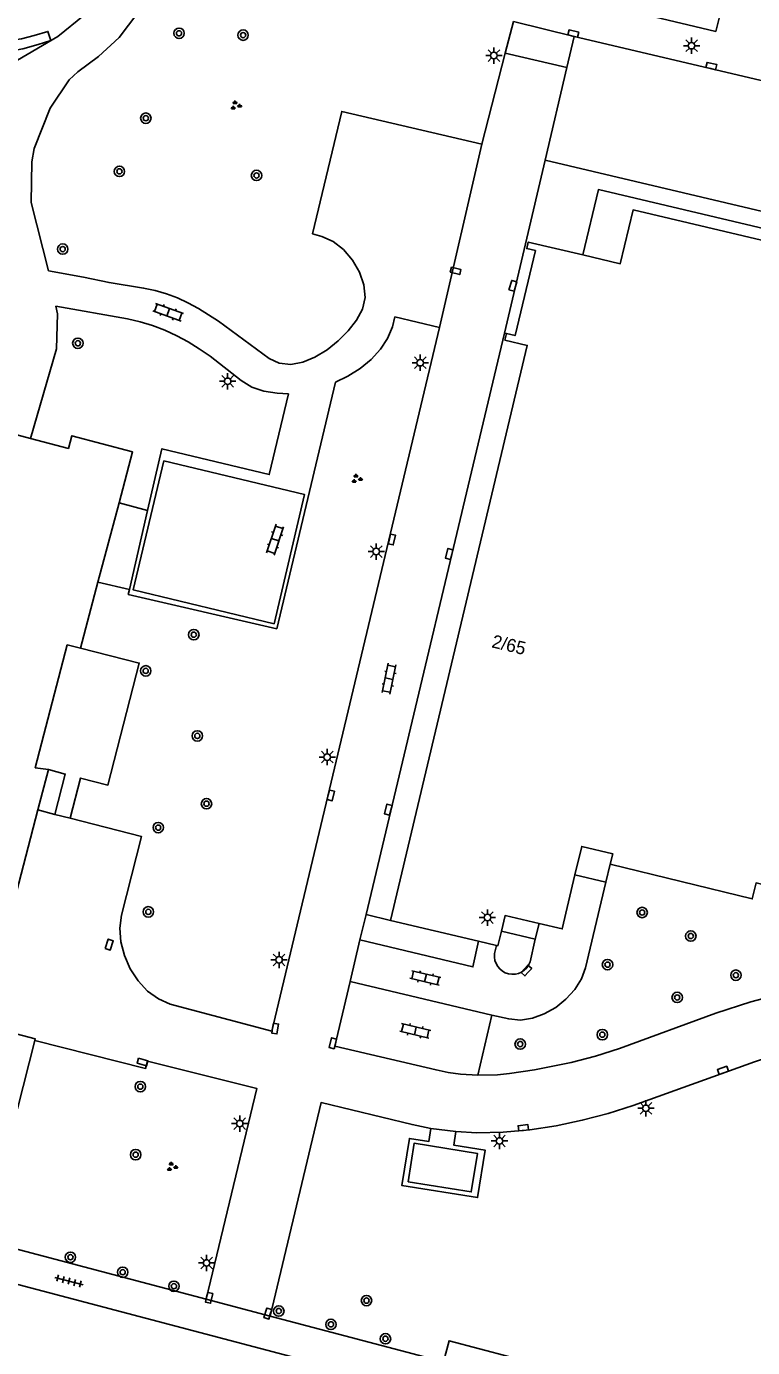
# Model space of a CAD drawing. Extents: x 131000 to 133014, y 396499 to 399001.
# Drawn here: x 131201.7 to 131257.2, y 397089.9 to 397191 of the extents above; entities that cross this region are included whole.
import ezdxf

# ---------------------------------------------------------------- set-up
doc = ezdxf.new("R2010")
doc.units = 0
for name, color, linetype in [('gg-afsc-hekwerk', 7, 'Continuous'), ('gg-anno-huisnummerreeks BGT', 7, 'Continuous'), ('gg-bbg-bijgebouw', 7, 'Continuous'), ('gg-bbg-gedigitaliseerde bijgebouw', 7, 'Continuous'), ('gg-bbg-hoofdgebouw', 7, 'Continuous'), ('gg-bbg-onder overbouw', 7, 'Continuous'), ('gg-bbg-pand overbouw', 7, 'Continuous'), ('gg-knt-verharding', 7, 'Continuous'), ('gt-grn-groengrens', 7, 'Continuous'), ('gt-grn-vlakafsluiter', 7, 'Continuous'), ('gt-symb-boom', 7, 'Continuous'), ('gt-symb-groenvak', 7, 'Continuous'), ('gt-symb-klinker verharding', 7, 'Continuous'), ('gt-symb-kolk', 7, 'Continuous'), ('gt-symb-kolk center center', 7, 'Continuous'), ('gt-symb-lichtmast', 7, 'Continuous'), ('gt-symb-tegel verharding', 7, 'Continuous')]:
    doc.layers.add(name, color=color, linetype=linetype)

# ---------------------------------------------------------------- blocks, each defined once
blk = doc.blocks.new('gt0-KOLKCC')
at = {"layer": 'gt-symb-kolk center center'}
blk.add_lwpolyline([(-0.37, 0.2), (0.38, 0.2), (0.38, -0.2), (-0.37, -0.2)], close=True, dxfattribs=at)
blk = doc.blocks.new('gt0-LMAST')
at = {"layer": 'gt-symb-lichtmast'}
for p, q in [((-0.18, 0.17), (-0.45, 0.44)), ((-0.01, 0.25), (-0.01, 0.62)), ((0.17, 0.17), (0.44, 0.44)), ((-0.26, 0), (-0.63, 0)), ((-0.18, -0.18), (-0.45, -0.45)), ((-0.01, -0.25), (-0.01, -0.63)), ((0.44, -0.45), (0.17, -0.18)), ((0.24, 0), (0.62, 0))]:
    blk.add_line(p, q, dxfattribs=at)
blk.add_circle((-0.01, 0), 0.25, dxfattribs=at)
blk = doc.blocks.new('gt0-KOLK')
at = {"layer": 'gt-symb-kolk'}
blk.add_lwpolyline([(0, 0), (0.38, 0), (0.38, 0.4), (-0.38, 0.4), (-0.38, 0), (0, 0)], dxfattribs=at)
blk = doc.blocks.new('gt0-GRVAK')
at = {"layer": 'gt-symb-groenvak'}
for p, q in [((-0.11, 0.19), (-0.23, 0.24)), ((-0.18, 0.15), (0.09, 0.15)), ((-0.09, 0.21), (-0.16, 0.32)), ((-0.05, 0.21), (-0.05, 0.39)), ((0, 0.21), (0.06, 0.32)), ((0.02, 0.19), (0.13, 0.24)), ((0.26, -0.05), (0.2, 0.06)), ((0.3, -0.05), (0.3, 0.13)), ((0.35, -0.05), (0.41, 0.06)), ((-0.24, -0.23), (-0.36, -0.18)), ((-0.32, -0.26), (-0.05, -0.26)), ((-0.23, -0.21), (-0.29, -0.09)), ((-0.18, -0.2), (-0.18, -0.02)), ((-0.14, -0.21), (-0.07, -0.09)), ((-0.12, -0.23), (0, -0.18)), ((0.24, -0.07), (0.12, -0.02)), ((0.17, -0.11), (0.44, -0.11)), ((0.37, -0.07), (0.49, -0.02))]:
    blk.add_line(p, q, dxfattribs=at)
blk = doc.blocks.new('gt0-BOOM')
at = {"layer": 'gt-symb-boom'}
for radius in [0.4, 0.2]:
    blk.add_circle((0, 0), radius, dxfattribs=at)
blk = doc.blocks.new('gt0-KL1')
at = {"layer": 'gt-symb-klinker verharding'}
for p, q in [((-1.15, 0.3), (1.15, 0.3)), ((-1, -0.3), (-1, 0.3)), ((-0.5, 0.3), (-0.5, 0.45)), ((0, -0.3), (0, 0.3)), ((0.5, 0.3), (0.5, 0.45)), ((1, -0.3), (1, 0.3)), ((-1.15, -0.3), (1.15, -0.3)), ((-0.5, -0.45), (-0.5, -0.3)), ((0.5, -0.45), (0.5, -0.3))]:
    blk.add_line(p, q, dxfattribs=at)
blk = doc.blocks.new('gt0-TEG1')
at = {"layer": 'gt-symb-tegel verharding'}
for p, q in [((-1.12, 0), (1.12, 0)), ((-0.9, -0.25), (-0.9, 0.25)), ((-0.45, -0.25), (-0.45, 0.25)), ((0, -0.25), (0, 0.25)), ((0.45, -0.25), (0.45, 0.25)), ((0.9, -0.25), (0.9, 0.25))]:
    blk.add_line(p, q, dxfattribs=at)

msp = doc.modelspace()

# ---------------------------------------------------------------- linework, layer by layer
at = {"layer": 'gg-afsc-hekwerk'}
for p, q in [((131238.02, 397121.75), (131240.61, 397121.14)), ((131240.61, 397121.14), (131240.21, 397119.41)), ((131237.5, 397120.05), (131237.65, 397120.67))]:
    msp.add_line(p, q, dxfattribs=at)
msp.add_arc((131238.89, 397119.86), 1.4, 172.3506, 341.0077, dxfattribs=at)
at = {"layer": 'gg-bbg-bijgebouw'}
msp.add_lwpolyline([(131230.88, 397102.57), (131231.34, 397105.52), (131236.18, 397104.75), (131235.72, 397101.8), (131230.88, 397102.57)], dxfattribs=at)
at = {"layer": 'gg-bbg-gedigitaliseerde bijgebouw'}
msp.add_lwpolyline([(131212.19, 397157.78), (131222.96, 397155.19), (131220.63, 397145.3), (131209.86, 397147.89), (131212.19, 397157.78)], dxfattribs=at)
at = {"layer": 'gg-bbg-hoofdgebouw'}
for p, q in [((131202, 397159.48), (131199.02, 397160.27)), ((131207.16, 397148.49), (131208.77, 397154.56)), ((131205.82, 397143.43), (131207.16, 397148.49)), ((131202.56, 397131.04), (131203.37, 397134.15)), ((131229.54, 397122.59), (131236.28, 397120.99)), ((131236.28, 397120.99), (131237.65, 397120.67)), ((131201.01, 397108.17), (131202.33, 397113.4))]:
    msp.add_line(p, q, dxfattribs=at)
for points in [[(131244.26, 397173.53), (131240.08, 397174.52), (131239.96, 397174.02), (131240.62, 397173.86), (131239.07, 397167.36), (131238.41, 397167.52)], [(131238.41, 397167.52), (131238.29, 397167.02), (131240, 397166.61), (131229.54, 397122.59)], [(131208.77, 397154.56), (131209.81, 397158.47), (131205.15, 397159.69), (131204.9, 397158.72), (131202, 397159.48)], [(131203.37, 397134.15), (131202.36, 397134.27), (131204.81, 397143.68), (131205.82, 397143.43)], [(131202.33, 397113.4), (131202.36, 397113.51), (131197.21, 397114.87), (131198.55, 397120), (131199.6, 397119.73), (131202.56, 397131.04)], [(131243.65, 397126.07), (131244.17, 397128.25), (131246.54, 397127.69), (131246.34, 397126.88)], [(131246.34, 397126.88), (131257.21, 397124.23), (131257.51, 397125.45), (131267.38, 397123.05), (131267.68, 397124.28), (131277.58, 397121.87), (131277.88, 397123.07), (131288.32, 397120.52), (131289.99, 397127.38), (131289.76, 397127.43)], [(131240.9, 397122.34), (131242.67, 397121.93), (131243.65, 397126.07)], [(131240.9, 397122.34), (131238.3, 397122.96), (131238.02, 397121.75)], [(131238.02, 397121.75), (131237.76, 397120.65), (131237.65, 397120.67)]]:
    msp.add_lwpolyline(points, dxfattribs=at)
at = {"layer": 'gg-bbg-onder overbouw'}
msp.add_lwpolyline([(131296.31, 397157.79), (131298.05, 397165.16), (131248.09, 397176.98), (131247.11, 397172.86), (131244.26, 397173.53)], dxfattribs=at)
at = {"layer": 'gg-bbg-pand overbouw'}
msp.add_lwpolyline([(131297.1, 397157.63), (131299.05, 397165.85), (131245.44, 397178.53), (131244.26, 397173.53)], dxfattribs=at)
at = {"layer": 'gg-knt-verharding'}
for p, q in [((131254.43, 397190.63), (131244.45, 397193)), ((131238.31, 397188.97), (131238.94, 397191.41)), ((131238.94, 397191.41), (131243.58, 397190.25)), ((131243.03, 397187.89), (131243.58, 397190.25)), ((131269.06, 397184.24), (131243.58, 397190.25)), ((131236.52, 397182.01), (131238.31, 397188.97)), ((131238.31, 397188.97), (131243.03, 397187.89)), ((131241.37, 397180.8), (131243.03, 397187.89)), ((131227.67, 397123.04), (131238.26, 397167.55)), ((131238.26, 397167.55), (131238.41, 397167.52)), ((131210.96, 397153.96), (131208.77, 397154.56)), ((131209.57, 397147.93), (131210.96, 397153.96)), ((131209.57, 397147.93), (131207.16, 397148.49)), ((131203.87, 397130.7), (131202.56, 397131.04)), ((131205.03, 397130.41), (131203.87, 397130.7)), ((131246.02, 397125.51), (131246.34, 397126.88)), ((131243.65, 397126.07), (131246.02, 397125.51)), ((131227.2, 397121.09), (131227.67, 397123.04)), ((131229.54, 397122.59), (131227.67, 397123.04)), ((131240.9, 397122.34), (131240.61, 397121.14)), ((131226.44, 397117.9), (131227.2, 397121.09)), ((131226.44, 397117.9), (131237.29, 397115.34)), ((131237.29, 397115.34), (131236.22, 397110.74)), ((131232.62, 397106.66), (131234.54, 397106.42)), ((131178.81, 397103.25), (131215.44, 397093.59)), ((131215.44, 397093.59), (131220.32, 397092.3))]:
    msp.add_line(p, q, dxfattribs=at)
for points in [[(131196.78, 397186.43), (131199.38, 397187.49), (131204.08, 397190.26), (131206.09, 397191.88), (131208.53, 397195.18), (131209.07, 397196.53), (131209.53, 397198.36)], [(131203.38, 397172.31), (131202.05, 397177.54), (131202.1, 397180.65), (131202.27, 397181.67), (131203.51, 397184.78), (131204.96, 397186.93), (131205.61, 397187.55), (131207.21, 397188.73), (131208.78, 397190.18), (131210.91, 397193.02), (131212.63, 397196.88), (131212.81, 397197.59)], [(131254.43, 397190.63), (131254.81, 397192.17), (131244.79, 397194.51), (131244.45, 397193)], [(131203.38, 397172.31), (131206.06, 397171.83), (131208.01, 397171.42), (131210.65, 397171), (131211.53, 397170.82), (131212.39, 397170.56), (131213.23, 397170.24), (131214.04, 397169.86), (131214.84, 397169.43), (131216.38, 397168.46), (131220.25, 397165.61), (131221.03, 397165.24), (131221.9, 397165.15), (131222.82, 397165.33), (131223.76, 397165.71), (131224.68, 397166.27), (131225.54, 397166.95), (131226.3, 397167.73), (131226.93, 397168.55), (131227.39, 397169.39), (131227.59, 397170.28), (131227.5, 397171.24), (131227.17, 397172.22), (131226.64, 397173.14), (131225.95, 397173.94), (131225.16, 397174.57), (131224.29, 397174.95), (131223.57, 397175.16), (131225.81, 397184.52), (131236.52, 397182.01)], [(131302.2, 397167.38), (131302.22, 397167.45), (131298.73, 397168.27), (131298.49, 397167.3), (131241.37, 397180.8)], [(131202, 397159.48), (131203.99, 397166.35), (131204.05, 397169.03), (131203.94, 397169.62)], [(131203.94, 397169.62), (131209.42, 397168.64), (131210.39, 397168.42), (131211.34, 397168.13), (131212.27, 397167.77), (131213.18, 397167.35), (131214.06, 397166.87), (131214.91, 397166.34), (131215.74, 397165.77), (131218.11, 397163.92), (131218.92, 397163.42), (131219.85, 397163.1), (131220.86, 397162.94), (131221.74, 397162.91)], [(131225.32, 397163.78), (131226.27, 397164.25), (131227.22, 397164.85), (131228.07, 397165.54), (131228.78, 397166.31), (131229.32, 397167.14), (131229.68, 397168.03), (131229.88, 397168.79), (131233.29, 397167.97)], [(131233.29, 397167.97), (131220.47, 397114.11), (131212.69, 397116.18), (131211.78, 397116.57), (131210.96, 397117.18), (131210.23, 397117.97), (131209.63, 397118.89), (131209.18, 397119.9), (131208.9, 397120.95), (131208.82, 397121.99), (131208.95, 397122.98), (131210.5, 397129), (131205.03, 397130.41)], [(131225.32, 397163.78), (131220.83, 397144.91), (131209.47, 397147.53), (131209.57, 397147.93)], [(131210.96, 397153.96), (131212.05, 397158.69), (131220.26, 397156.72), (131221.74, 397162.91)], [(131205.03, 397130.41), (131205.82, 397133.48), (131207.92, 397132.95), (131210.31, 397142.29), (131205.82, 397143.43)], [(131203.87, 397130.7), (131204.65, 397133.79), (131203.37, 397134.15)], [(131237.29, 397115.34), (131238.58, 397115.04), (131239.47, 397114.95), (131240.39, 397115.1), (131241.3, 397115.43), (131242.18, 397115.93), (131242.96, 397116.56), (131243.63, 397117.3), (131244.14, 397118.11), (131244.46, 397118.96), (131246.02, 397125.51)], [(131227.2, 397121.09), (131235.84, 397119.03), (131236.28, 397120.99)], [(131236.22, 397110.74), (131234.89, 397110.82), (131233.95, 397110.95), (131233.03, 397111.14), (131225.27, 397112.96), (131226.44, 397117.9)], [(131236.22, 397110.74), (131237.72, 397110.77), (131238.65, 397110.87), (131240.55, 397111.15), (131243.37, 397111.72), (131245.23, 397112.2), (131247.05, 397112.77), (131254.43, 397115.49), (131257.11, 397116.34), (131258.93, 397116.83), (131260.76, 397117.25), (131262.6, 397117.62), (131264.44, 397117.88), (131265.37, 397117.95), (131266.3, 397117.97), (131267.23, 397117.93), (131301.27, 397115.35)], [(131215.44, 397093.59), (131219.3, 397109.72), (131210.95, 397111.8), (131210.8, 397111.25), (131202.33, 397113.4)], [(131234.54, 397106.42), (131236.14, 397106.33), (131238.16, 397106.37), (131240.19, 397106.56), (131242.21, 397106.87), (131244.21, 397107.29), (131246.18, 397107.81), (131248.1, 397108.41), (131257.39, 397111.76), (131259.12, 397112.35), (131260.9, 397112.85), (131262.7, 397113.24), (131264.53, 397113.49), (131265.44, 397113.54), (131266.36, 397113.55), (131267.27, 397113.5), (131282.86, 397112.26)], [(131220.32, 397092.3), (131224.23, 397108.64), (131231.19, 397106.95), (131232.62, 397106.66)], [(131151.22, 397107.85), (131239.9, 397084.45), (131240.99, 397088.56), (131234.02, 397090.4), (131233.6, 397088.8), (131220.32, 397092.3)], [(131234.54, 397106.42), (131234.39, 397105.37), (131236.77, 397105), (131236.2, 397101.37), (131230.41, 397102.29), (131230.98, 397105.9), (131232.47, 397105.67), (131232.62, 397106.66)]]:
    msp.add_lwpolyline(points, dxfattribs=at)
at = {"layer": 'gt-grn-groengrens'}
msp.add_lwpolyline([(131191.56, 397191.89), (131193.46, 397191.01), (131196.16, 397190.11), (131198.88, 397189.88), (131199.81, 397189.88), (131200.44, 397189.96), (131201.3, 397190.07), (131202.28, 397190.32), (131203.33, 397190.65), (131203.54, 397189.95), (131202.58, 397189.65), (131201.42, 397189.3), (131200.11, 397189.08), (131197.55, 397189.16), (131195.65, 397189.44), (131193.89, 397189.98), (131192.03, 397190.97), (131190.1, 397192.26)], dxfattribs=at)
at = {"layer": 'gt-grn-vlakafsluiter'}
for p, q in [((131236.52, 397182.01), (131233.29, 397167.97)), ((131241.37, 397180.8), (131238.26, 397167.55))]:
    msp.add_line(p, q, dxfattribs=at)

# ---------------------------------------------------------------- block references
at = {"layer": 'gt-symb-boom'}
for p in [(131213.36, 397190.5), (131218.26, 397190.36), (131210.82, 397184), (131208.8, 397179.93), (131219.29, 397179.62), (131204.46, 397173.98), (131205.62, 397166.77), (131214.49, 397144.46), (131210.81, 397141.69), (131214.76, 397136.71), (131215.46, 397131.52), (131211.77, 397129.69), (131211.01, 397123.24), (131248.79, 397123.19), (131252.51, 397121.39), (131246.14, 397119.2), (131255.96, 397118.39), (131251.47, 397116.69), (131245.74, 397113.84), (131239.46, 397113.12), (131210.4, 397109.86), (131210.04, 397104.65), (131205.05, 397096.8), (131209.05, 397095.65), (131212.97, 397094.58), (131227.7, 397093.48), (131220.99, 397092.68), (131224.98, 397091.66), (131229.15, 397090.56)]:
    msp.add_blockref('gt0-BOOM', p, dxfattribs=at)
at = {"layer": 'gt-symb-groenvak'}
for p in [(131217.69, 397184.97), (131226.94, 397156.39), (131212.81, 397103.72)]:
    msp.add_blockref('gt0-GRVAK', p, dxfattribs=at)
at = {"layer": 'gt-symb-klinker verharding'}
for p, rotation in [((131212.53, 397169.14), -19.63070227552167), ((131220.71, 397151.73), 71.58316555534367), ((131229.43, 397141.09), 78.28547478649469), ((131232.21, 397118.18), -13.355340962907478), ((131231.43, 397114.13), -13.355340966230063)]:
    msp.add_blockref('gt0-KL1', p, dxfattribs=dict(at, rotation=rotation))
at = {"layer": 'gt-symb-kolk'}
for p, rotation in [((131243.48, 397190.29), -12.535023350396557), ((131254.04, 397187.8), -13.174926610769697), ((131229.45, 397151.79), -103.17492660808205), ((131234.22, 397150.59), 75.35262472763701), ((131224.77, 397132.2), -103.70288996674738), ((131229.56, 397131.02), 75.40804379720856), ((131240.08, 397118.62), 47.47195594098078), ((131220.52, 397114.34), -99.66950525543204), ((131225.32, 397113.13), 75.35262472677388), ((131255.04, 397110.92), 19.757899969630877), ((131239.72, 397106.51), 6.314884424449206), ((131215.47, 397093.73), -102.64685349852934), ((131220.34, 397092.43), 73.43253308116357)]:
    msp.add_blockref('gt0-KOLK', p, dxfattribs=dict(at, rotation=rotation))
at = {"layer": 'gt-symb-kolk center center'}
for p, rotation in [((131234.51, 397172.31), -14.244742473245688), ((131238.9, 397171.16), 73.26783977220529), ((131208.02, 397120.73), 72.23567662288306), ((131210.56, 397111.74), -15.48118592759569)]:
    msp.add_blockref('gt0-KOLKCC', p, dxfattribs=dict(at, rotation=rotation))
at = {"layer": 'gt-symb-lichtmast'}
for p in [(131252.58, 397189.55), (131237.45, 397188.8), (131231.82, 397165.28), (131217.09, 397163.86), (131228.45, 397150.83), (131224.7, 397135.09), (131236.96, 397122.81), (131221.02, 397119.57), (131249.08, 397108.2), (131218.01, 397107.03), (131237.88, 397105.7), (131215.48, 397096.36)]:
    msp.add_blockref('gt0-LMAST', p, dxfattribs=at)
at = {"layer": 'gt-symb-tegel verharding', "rotation": -14.77272395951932}
msp.add_blockref('gt0-TEG1', (131204.94, 397094.97), dxfattribs=at)

# ---------------------------------------------------------------- texts
at = {"layer": 'gg-anno-huisnummerreeks BGT'}
msp.add_text('2/65', height=1, rotation=346.6, dxfattribs=at).set_placement((131237.22, 397143.5))

doc.saveas('drawing.dxf')
